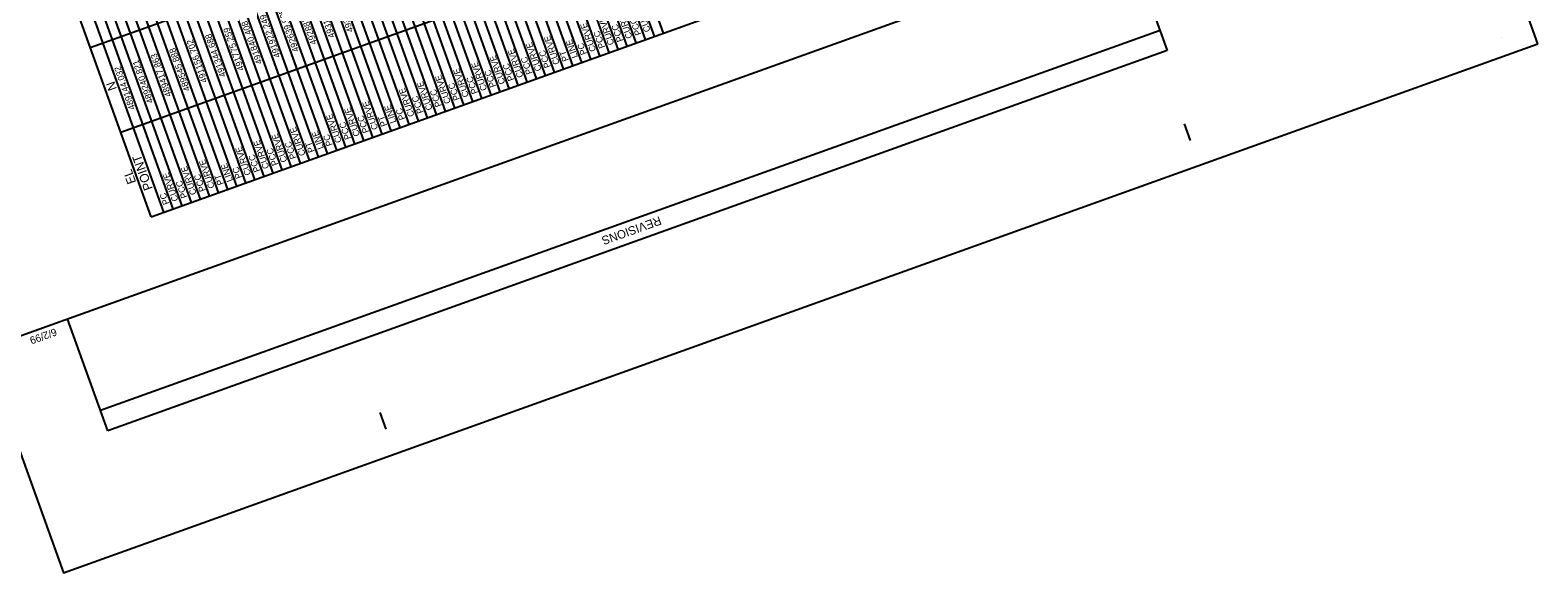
# Model space of a CAD drawing. Extents: x 482558 to 486111, y 507483 to 511816.
# Drawn here: x 483767 to 486111, y 507483 to 508328 of the extents above; entities that cross this region are included whole.
import ezdxf

# ---------------------------------------------------------------- set-up
doc = ezdxf.new("R2010")
doc.units = 0
for name, color, linetype in [('CTL Sheet Border CELL', 7, 'Continuous'), ('CTL Sheet Notes CELL', 7, 'Continuous'), ('CTL Sheet Table Cell', 7, 'Continuous'), ('CTL Sheet Text', 7, 'Continuous'), ('Sheet Block Revision CELL', 7, 'Continuous'), ('Sheet Plot Border Outside CELL', 7, 'Continuous')]:
    doc.layers.add(name, color=color, linetype=linetype)

msp = doc.modelspace()

# ---------------------------------------------------------------- linework, layer by layer
at = {"layer": 'CTL Sheet Border CELL'}
for p, q in [((486054.9, 508316.6), (486054.9, 508316.6)), ((486111.4, 508306.3), (486111.4, 508306.3)), ((485571.3, 508155.9), (485561.9, 508182)), ((484320.7, 507706.9), (484311.3, 507732.9))]:
    msp.add_line(p, q, dxfattribs=at)
msp.add_lwpolyline([(482623.2, 510976.5), (483745.8, 507849.9), (485934.4, 508635.7), (484811.7, 511762.3)], close=True, dxfattribs=at)
at = {"layer": 'CTL Sheet Table Cell'}
for p, q in [((484695.3, 508302.9), (484222.2, 509620.5)), ((484709.4, 508307.9), (484236.3, 509625.6)), ((484723.6, 508313), (484250.5, 509630.7)), ((484737.7, 508318.1), (484264.6, 509635.7)), ((484751.8, 508323.2), (484278.7, 509640.8)), ((484638.9, 508282.6), (484165.8, 509600.2)), ((484653, 508287.7), (484179.9, 509605.3)), ((484667.1, 508292.7), (484194, 509610.4)), ((484681.2, 508297.8), (484208.1, 509615.4)), ((484568.3, 508257.3), (484095.2, 509574.9)), ((484582.4, 508262.3), (484109.3, 509580)), ((484596.5, 508267.4), (484123.4, 509585)), ((484610.6, 508272.5), (484137.5, 509590.1)), ((484624.7, 508277.5), (484151.6, 509595.2)), ((484497.7, 508231.9), (484024.6, 509549.6)), ((484511.8, 508237), (484038.7, 509554.6)), ((484525.9, 508242.1), (484052.8, 509559.7)), ((484540, 508247.1), (484066.9, 509564.8)), ((484554.1, 508252.2), (484081, 509569.8)), ((484441.2, 508211.6), (483968.1, 509529.3)), ((484455.3, 508216.7), (483982.2, 509534.3)), ((484469.4, 508221.8), (483996.3, 509539.4)), ((484483.6, 508226.8), (484010.5, 509544.5)), ((484370.6, 508186.3), (483897.5, 509503.9)), ((484384.7, 508191.4), (483911.6, 509509)), ((484398.9, 508196.4), (483925.8, 509514.1)), ((484413, 508201.5), (483939.9, 509519.1)), ((484427.1, 508206.6), (483954, 509524.2)), ((484314.1, 508166), (483841, 509483.7)), ((484328.3, 508171.1), (483855.2, 509488.7)), ((484342.4, 508176.2), (483869.3, 509493.8)), ((484356.5, 508181.2), (483883.4, 509498.9)), ((484243.6, 508140.7), (483770.5, 509458.3)), ((484257.7, 508145.7), (483784.6, 509463.4)), ((484271.8, 508150.8), (483798.7, 509468.4)), ((484285.9, 508155.9), (483812.8, 509473.5)), ((484300, 508160.9), (483826.9, 509478.6)), ((484173, 508115.3), (483699.9, 509433)), ((484187.1, 508120.4), (483714, 509438)), ((484201.2, 508125.5), (483728.1, 509443.1)), ((484215.3, 508130.5), (483742.2, 509448.2)), ((484229.4, 508135.6), (483756.3, 509453.2)), ((484116.5, 508095.1), (483643.4, 509412.7)), ((484130.6, 508100.1), (483657.5, 509417.8)), ((484144.7, 508105.2), (483671.6, 509422.8)), ((484158.9, 508110.3), (483685.8, 509427.9)), ((484045.9, 508069.7), (483572.8, 509387.3)), ((484060, 508074.8), (483586.9, 509392.4)), ((484074.1, 508079.8), (483601, 509397.5)), ((484088.3, 508084.9), (483615.2, 509402.6)), ((484102.4, 508090), (483629.3, 509407.6)), ((483974.9, 508044.2), (483501.8, 509361.8)), ((483989.4, 508049.4), (483516.3, 509367.1)), ((484003.6, 508054.5), (483530.5, 509372.1)), ((484017.7, 508059.6), (483544.6, 509377.2)), ((484031.8, 508064.6), (483558.7, 509382.3)), ((483955.1, 508037.1), (483482, 509354.7)), ((483860.5, 508300.6), (485588.9, 508921.2)), ((483907.8, 508168.9), (485636.2, 508789.5)), ((483955.1, 508037.1), (485683.6, 508657.7))]:
    msp.add_line(p, q, dxfattribs=at)
at = {"layer": 'Sheet Block Revision CELL'}
for p, q in [((485472.6, 508469.9), (485535.2, 508295.9)), ((485524, 508327.1), (483876.4, 507735.6)), ((485535.2, 508295.9), (483887.7, 507704.3)), ((483887.7, 507704.3), (483825.1, 507878.4))]:
    msp.add_line(p, q, dxfattribs=at)
at = {"layer": 'Sheet Plot Border Outside CELL'}
msp.add_lwpolyline([(486111.4, 508306.3), (484851.1, 511816.5), (482558.3, 510993.2), (483818.6, 507483.1)], close=True, dxfattribs=at)

# ---------------------------------------------------------------- texts
at = {"layer": 'CTL Sheet Border CELL'}
msp.add_text('6/2/99', height=11.63, rotation=199.7508, dxfattribs=at).set_placement((483805.9, 507864.1))
at = {"layer": 'CTL Sheet Notes CELL'}
for s, p in [('N', (483902.1, 508236.4)), ('POINT', (483957.9, 508081.2)), ('EL', (483932, 508091.1))]:
    msp.add_text(s, height=14, rotation=109.7508, dxfattribs=at).set_placement(p)
at = {"layer": 'CTL Sheet Text'}
for s, p in [('493168.623', (484241.2, 508317.5)), ('493283.236', (484269.9, 508326.2)), ('492639.905', (484185.3, 508295.6)), ('492882.971', (484213, 508307.1)), ('CURVE', (484703.7, 508316.5)), ('CURVE', (484731.9, 508326.7)), ('491775.259', (484100.1, 508266.5)), ('491840.408', (484128.3, 508276.6)), ('491922.249', (484156.6, 508286.8)), ('CURVE', (484647.2, 508296.2)), ('CURVE', (484675.5, 508306.4)), ('PCC', (484689.6, 508311.4)), ('PCC', (484717.8, 508321.6)), ('491156.702', (484043, 508247.8)), ('491344.688', (484071.8, 508256.6)), ('CURVE', (484562.5, 508265.8)), ('CURVE', (484590.8, 508276)), ('LINE', (484619, 508286.1)), ('PC', (484633.1, 508291.2)), ('PCC', (484661.4, 508301.3)), ('489417.863', (483987.1, 508226)), ('489545.888', (484016, 508234.5)), ('CURVE', (484506.1, 508245.5)), ('CURVE', (484534.3, 508255.7)), ('PCC', (484548.4, 508260.8)), ('PCC', (484576.7, 508270.9)), ('PT', (484604.9, 508281)), ('489144.032', (483930.6, 508205.8)), ('489240.821', (483958.9, 508215.8)), ('CURVE', (484449.6, 508225.3)), ('CURVE', (484477.8, 508235.4)), ('PCC', (484491.9, 508240.5)), ('PCC', (484520.2, 508250.6)), ('CURVE', (484364.9, 508194.9)), ('CURVE', (484393.1, 508205)), ('CURVE', (484421.4, 508215.1)), ('PCC', (484435.5, 508220.2)), ('PCC', (484463.7, 508230.3)), ('CURVE', (484308.4, 508174.6)), ('PCC', (484379, 508199.9)), ('PCC', (484407.2, 508210.1)), ('CURVE', (484251.9, 508154.3)), ('CURVE', (484280.2, 508164.4)), ('PCC', (484294.3, 508169.5)), ('PT', (484322.5, 508179.7)), ('LINE', (484336.7, 508184.7)), ('PC', (484350.8, 508189.8)), ('CURVE', (484167.2, 508123.9)), ('CURVE', (484195.5, 508134)), ('LINE', (484223.7, 508144.2)), ('PCC', (484266.1, 508159.4)), ('CURVE', (484110.8, 508103.6)), ('CURVE', (484139, 508113.8)), ('PCC', (484153.1, 508118.8)), ('PCC', (484181.4, 508129)), ('PT', (484209.6, 508139.1)), ('PC', (484237.8, 508149.2)), ('CURVE', (484054.3, 508083.3)), ('LINE', (484082.5, 508093.5)), ('PCC', (484124.9, 508108.7)), ('CURVE', (483997.8, 508063.1)), ('CURVE', (484026.1, 508073.2)), ('PCC', (484040.2, 508078.3)), ('PT', (484068.4, 508088.4)), ('PC', (484096.7, 508098.5)), ('PC', (483983.7, 508058)), ('PCC', (484011.9, 508068.1))]:
    msp.add_text(s, height=10, rotation=109.7508, dxfattribs=at).set_placement(p)
at = {"layer": 'Sheet Block Revision CELL'}
msp.add_text('REVISIONS', height=13.28, rotation=199.7508, dxfattribs=at).set_placement((484745.5, 508038.3))

doc.saveas('drawing.dxf')
